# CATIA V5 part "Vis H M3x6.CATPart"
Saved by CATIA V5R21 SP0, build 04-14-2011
Part number: Vis H M3x6
Material "Acier": density 7860 kg/m3, Young's modulus 2e+11 Pa, Poisson ratio 0.266, thermal expansion 1.17e-05 1/K
Bounding box of the stored display mesh (mm): x -2.5 to 2.5, y -2.887 to 2.887, z 0 to 8
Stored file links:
  C:\Users\Olivier\Desktop\redaction CATIA (local)\CATIA\DONNEES\Exercice assemblage 3 (Pompe de ventilation)\Assemblage ensemble bloc moteur (Product inclus)\Vis H M3x6.CATPart
  C:\Program Files\Dassault Systemes\B21\win_b64\startup\materials\French\Catalog.CATMaterial
  C:\Users\Olivier\Desktop\redaction CATIA (local)\CATIA\DONNEES\Exercice assemblage 3 (Pompe de ventilation)\Assemblage ensemble bloc moteur (Product inclus)\CATIA_EnvironmentMap_Satin_512x512.jpg
  C:\Users\Olivier\Desktop\redaction CATIA (local)\pompe à moteur de ventilation refait\Pompe_a_moteur_de_ventilation.CATProduct
  C:\Users\Olivier\Desktop\redaction CATIA (local)\pompe à moteur de ventilation refait\Ecrou a collerette M5.CATPart
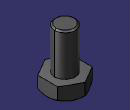
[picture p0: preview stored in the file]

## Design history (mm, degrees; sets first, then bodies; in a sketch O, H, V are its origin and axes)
Body1 (main body), material "Acier"
  Sketch1 on xy-plane, origin (0, 0, 0), H (1, 0, 0), V (0, 1, 0)
    circle A1 centre (0, 0) radius 1.5
    point P1 (2.5, -1.4434)
    point P2 (2.5, 1.4434)
    point P3 (0, 2.8868)
    point P4 (-2.5, 1.4434)
    point P5 (-2.5, -1.4434)
    point P6 (0, -2.8868)
    point P7 (2.5, 0)
    line L1 (2.5, -1.4434) -> (2.5, 1.4434)
    line L2 (2.5, 1.4434) -> (0, 2.8868)
    line L3 (0, 2.8868) -> (-2.5, 1.4434)
    line L4 (-2.5, 1.4434) -> (-2.5, -1.4434)
    line L5 (-2.5, -1.4434) -> (0, -2.8868)
    line L6 (0, -2.8868) -> (2.5, -1.4434)
    construction line L7 (0, 0) -> (2.5, 0)
    construction circle A2 centre (0, 0) radius 2.8868
    construction arc A3 centre (-2.5, -1.4434) radius 2.8868 from (-2.5, 1.4434) to (0, -2.8868) cw
    construction arc A4 centre (2.5, 1.4434) radius 2.8868 from (0, 2.8868) to (2.5, -1.4434) ccw
    distance L1 L4 = 5
    horizontal: L7 H
    coincidence: A2 P1, A2 P2, A2 P3, A2 P4, A2 P5, A2 P6, A3 O, A4 O
    midpoint: P7 L1
  MultiPad1: profile Sketch1, domains (length 2; length 8)
  Sketch2 on yz-plane, origin (0, 0, 0), H (0, 1, 0), V (0, 0, 1)
    line L1 (2.509, 0) -> (2.9319, 0.3605)
    point P1 (2.509, 0)
    line L2 (2.9319, 0.3605) -> (2.9319, 0)
    point P3 (2.9319, 0)
    line L3 (2.9319, 0) -> (2.509, 0)
    coincidence: P1 H, P3 H
    vertical: L2 V
    horizontal: L3 H
  Groove1: profile Sketch2, axis Sketch2.V, angle 360
  Chamfer1: length 0.2, angle 45, on face of MultiPad1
